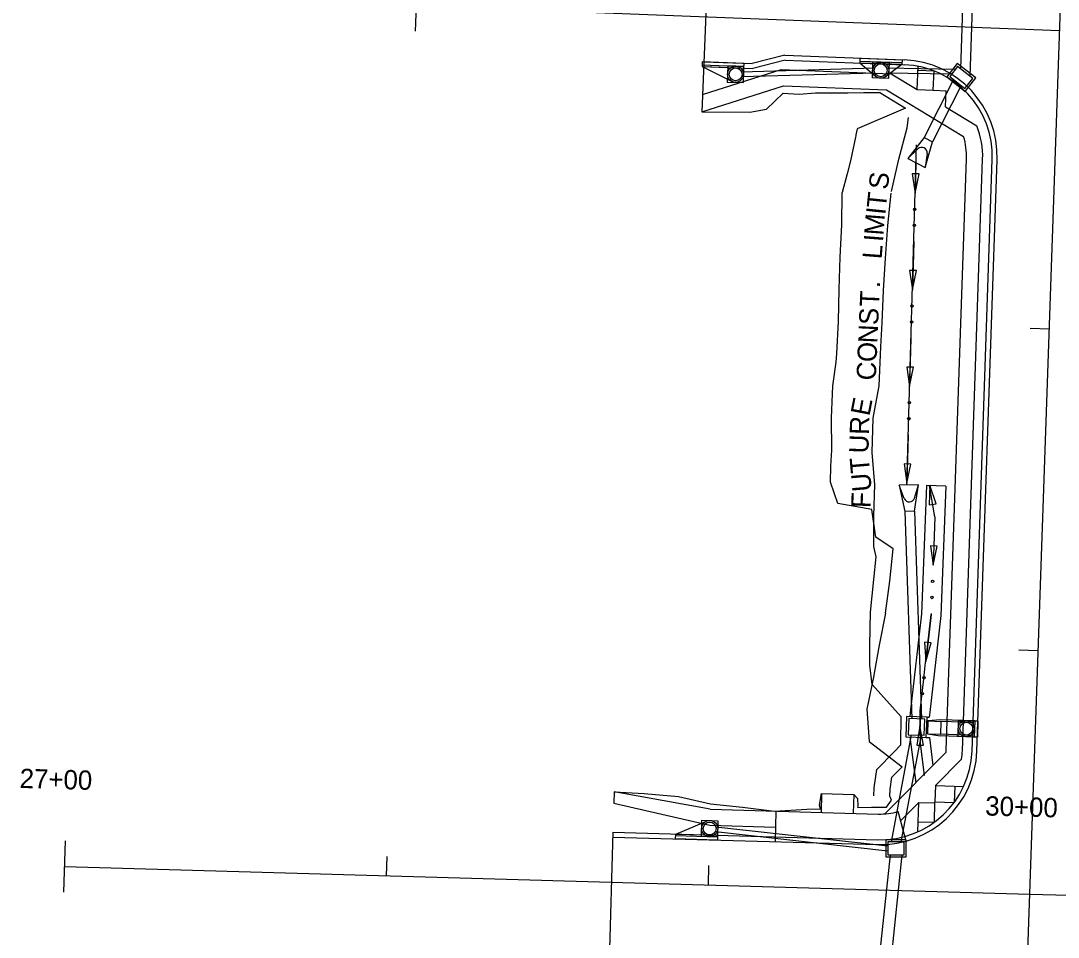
# Model space of a CAD drawing. Extents: x 979959 to 994833, y 1835619 to 1845316.
# Drawn here: x 992166.1 to 992488.3, y 1842864.9 to 1843149.5 of the extents above; entities that cross this region are included whole.
import ezdxf

# ---------------------------------------------------------------- set-up
doc = ezdxf.new("R2010")
doc.units = 0
for name, color, linetype in [('Future 5 Lane Construction Limits', 7, 'Continuous'), ('R_Drainage', 7, 'Continuous'), ('R_Horz Alg', 7, 'Continuous'), ('R_Horz Alg Stationing', 7, 'Continuous'), ('R_Proposed Const Limits', 7, 'Continuous'), ('R_Proposed Road', 7, 'Continuous'), ('R_Special Ditch', 7, 'Continuous')]:
    doc.layers.add(name, color=color, linetype=linetype)

msp = doc.modelspace()

# ---------------------------------------------------------------- linework, layer by layer
at = {"layer": 'Future 5 Lane Construction Limits'}
for points in [[(992436.53, 1843096.52), (992438.78, 1843106.54), (992441.33, 1843116.29), (992441.82, 1843119.43)], [(992430.96, 1842986.25), (992431, 1842994.08), (992431.02, 1842995.67), (992431.34, 1843005.42), (992430.48, 1843015.44), (992430.78, 1843026.13), (992432.7, 1843036.1), (992433.09, 1843045.73), (992433.21, 1843048.3), (992433.55, 1843055.72), (992433.98, 1843065.76), (992434.62, 1843075.83), (992435.4, 1843085.91), (992436.43, 1843095.94)], [(992439.42, 1842924.66), (992439.43, 1842925.27), (992439.46, 1842933.33), (992430.48, 1842943.39), (992429.75, 1842949.42), (992429.79, 1842955.63), (992429.99, 1842965.87), (992431.02, 1842976.06), (992431.75, 1842983.02), (992430.96, 1842986.25)], [(992431.02, 1842908.86), (992431.09, 1842911.37), (992431.93, 1842917.04), (992437.28, 1842922.47), (992439.42, 1842924.66)]]:
    msp.add_lwpolyline(points, dxfattribs=at)
at = {"layer": 'R_Drainage'}
for p, q in [((992458.79, 1843162.87), (992457.93, 1843134.59)), ((992461.79, 1843162.77), (992460.86, 1843132.3)), ((992377.69, 1843135.78), (992390.68, 1843135.27)), ((992426.72, 1843136.37), (992431.51, 1843132.24)), ((992439.73, 1843136.39), (992426.74, 1843136.87)), ((992439.72, 1843135.89), (992434.63, 1843132.12)), ((992377.67, 1843135.28), (992386.97, 1843130.63)), ((992389.92, 1843133.67), (992431.27, 1843134.83)), ((992389.96, 1843132.17), (992431.31, 1843133.33)), ((992434.99, 1843133.35), (992455.23, 1843132.98)), ((992435.01, 1843134.85), (992456.38, 1843134.46)), ((992385.49, 1843130.47), (992390.48, 1843130.28)), ((992435.55, 1843131.54), (992430.55, 1843131.73)), ((992455.74, 1843131.23), (992446.61, 1843113.29)), ((992458.13, 1843129.36), (992449.28, 1843111.93)), ((992446.61, 1843113.29), (992441.58, 1843106.7)), ((992446.61, 1843113.29), (992449.28, 1843111.93)), ((992446.93, 1843103.98), (992449.28, 1843111.93)), ((992444.72, 1843109.74), (992441.58, 1843106.7)), ((992441.58, 1843106.7), (992446.93, 1843103.98)), ((992447.53, 1843108.31), (992446.93, 1843103.98)), ((992444.91, 1843005.46), (992438.91, 1843005.26)), ((992438.91, 1843005.26), (992440.68, 1842997.16)), ((992440.47, 1843001.18), (992438.91, 1843005.26)), ((992443.62, 1843001.28), (992444.91, 1843005.46)), ((992443.68, 1842997.26), (992444.91, 1843005.46)), ((992447.37, 1843005.2), (992445.81, 1842965.33)), ((992453.37, 1843004.96), (992447.37, 1843005.2)), ((992453.37, 1843004.96), (992451.79, 1842964.87)), ((992443.68, 1842997.26), (992440.68, 1842997.16)), ((992440.68, 1842997.16), (992442.84, 1842932.78)), ((992443.68, 1842997.26), (992445.84, 1842932.68)), ((992447.53, 1842933.29), (992448.19, 1842933.27)), ((992447.82, 1842932.1), (992447.68, 1842928.1)), ((992451.84, 1842932.47), (992447.82, 1842932.1)), ((992447.82, 1842932.1), (992451.81, 1842931.97)), ((992451.81, 1842931.97), (992451.68, 1842927.97)), ((992461.81, 1842931.63), (992451.81, 1842931.97)), ((992462.33, 1842932.11), (992451.84, 1842932.47)), ((992457.16, 1842927.29), (992457.33, 1842932.28)), ((992461.81, 1842931.63), (992461.67, 1842927.63)), ((992462.33, 1842932.11), (992462.16, 1842927.11)), ((992442.65, 1842927.79), (992436.36, 1842894.55)), ((992445.68, 1842927.68), (992439.41, 1842894.55)), ((992447.31, 1842926.96), (992448.27, 1842926.93)), ((992447.68, 1842928.1), (992451.66, 1842927.47)), ((992447.68, 1842928.1), (992451.68, 1842927.97)), ((992462.16, 1842927.11), (992451.66, 1842927.47)), ((992461.67, 1842927.63), (992451.68, 1842927.97)), ((992461.66, 1842927.13), (992463.16, 1842927.08)), ((992444.01, 1842912.95), (992449.37, 1842918.32)), ((992369.48, 1842897), (992379.07, 1842901.01)), ((992377.61, 1842901.27), (992382.61, 1842901.13)), ((992381.8, 1842897.75), (992435.39, 1842891.79)), ((992381.96, 1842899.24), (992435.39, 1842893.3)), ((992369.47, 1842896.5), (992382.46, 1842896.13)), ((992436.04, 1842890.55), (992432.38, 1842855.46)), ((992439.73, 1842890.55), (992436.03, 1842855.08))]:
    msp.add_line(p, q, dxfattribs=at)
for points in [[(992377.67, 1843135.28), (992390.66, 1843134.77), (992390.72, 1843136.27), (992377.73, 1843136.77)], [(992439.72, 1843135.89), (992426.72, 1843136.37), (992426.78, 1843137.87), (992439.77, 1843137.39)], [(992435.55, 1843131.54), (992430.55, 1843131.73), (992430.74, 1843136.72), (992435.74, 1843136.54)], [(992453.64, 1843132.03), (992459.42, 1843127.51), (992462.7, 1843131.72), (992456.92, 1843136.23)], [(992385.49, 1843130.47), (992390.48, 1843130.28), (992390.68, 1843135.27), (992385.68, 1843135.47)], [(992454.57, 1843132.14), (992459.3, 1843128.45), (992461.76, 1843131.6), (992457.03, 1843135.29)], [(992447.53, 1842933.29), (992441.2, 1842933.51), (992440.98, 1842927.18), (992447.31, 1842926.96)], [(992446.84, 1842932.65), (992441.84, 1842932.82), (992441.67, 1842927.82), (992446.66, 1842927.65)], [(992457.16, 1842927.29), (992457.33, 1842932.28), (992462.33, 1842932.11), (992462.16, 1842927.11)], [(992461.66, 1842927.13), (992461.83, 1842932.13), (992463.33, 1842932.08), (992463.16, 1842927.08)], [(992377.61, 1842901.27), (992382.61, 1842901.13), (992382.46, 1842896.13), (992377.47, 1842896.27)], [(992369.48, 1842897), (992382.48, 1842896.63), (992382.44, 1842895.13), (992369.44, 1842895.5)], [(992441.05, 1842889.88), (992441.05, 1842895.22), (992434.72, 1842895.22), (992434.72, 1842889.88)], [(992440.39, 1842890.55), (992440.39, 1842894.55), (992435.39, 1842894.55), (992435.39, 1842890.55)]]:
    msp.add_lwpolyline(points, close=True, dxfattribs=at)
for points in [[(992445.81, 1842965.33), (992444.68, 1842955.47), (992442.41, 1842935.54), (992442.17, 1842933.47)], [(992451.79, 1842964.87), (992450.64, 1842954.79), (992448.37, 1842934.86), (992448.19, 1842933.27)], [(992463.16, 1842927.08), (992463.33, 1842932.08), (992461.83, 1842932.13), (992461.66, 1842927.13)], [(992442.19, 1842927.14), (992444.01, 1842912.93)], [(992448.27, 1842926.93), (992449.37, 1842918.32)]]:
    msp.add_lwpolyline(points, dxfattribs=at)
for centre, radius in [((992433.15, 1843134.13), 2.5), ((992433.15, 1843134.13), 2.5), ((992433.15, 1843134.13), 2), ((992433.15, 1843134.13), 2), ((992388.08, 1843132.87), 2.5), ((992388.08, 1843132.87), 2.5), ((992388.08, 1843132.87), 2), ((992388.08, 1843132.87), 2), ((992459.74, 1842929.7), 2.5), ((992459.74, 1842929.7), 2.5), ((992459.74, 1842929.7), 2), ((992459.74, 1842929.7), 2), ((992380.04, 1842898.7), 2.5), ((992380.04, 1842898.7), 2.5), ((992380.04, 1842898.7), 2), ((992380.04, 1842898.7), 2)]:
    msp.add_circle(centre, radius, dxfattribs=at)
for centre, start, end in [((992445.88, 1843108.54), 352.0964, 134.0112), ((992442.03, 1843001.77), 200.9572, 342.8719)]:
    msp.add_arc(centre, 1.67, start, end, dxfattribs=at)
at = {"layer": 'R_Horz Alg'}
for p, q in [((992476.02, 1842777.04), (992513.51, 1843870.41)), ((992288.84, 1843154.22), (992488.69, 1843146.49)), ((992179.62, 1842886.9), (992479.5, 1842878.36)), ((992479.5, 1842878.36), (992779.37, 1842869.83))]:
    msp.add_line(p, q, dxfattribs=at)
at = {"layer": 'R_Horz Alg Stationing'}
for points in [[(992289.15, 1843162.21), (992288.53, 1843146.23)], [(992479.52, 1843054.1), (992485.51, 1843053.89)], [(992476.09, 1842954.16), (992482.09, 1842953.95)], [(992179.84, 1842894.9), (992179.39, 1842878.9)], [(992279.75, 1842890.05), (992279.58, 1842884.05)], [(992379.71, 1842887.21), (992379.54, 1842881.21)]]:
    msp.add_lwpolyline(points, dxfattribs=at)
at = {"layer": 'R_Proposed Const Limits'}
for points in [[(992377.63, 1843121.23), (992392.51, 1843121.11), (992397.68, 1843122.08), (992402.87, 1843126.97), (992407.87, 1843126.72), (992412.89, 1843127.14), (992417.89, 1843127.14), (992422.89, 1843127.16), (992427.9, 1843127.19), (992432.9, 1843127.23), (992440.86, 1843122.31)], [(992440.86, 1843122.31), (992425.86, 1843115.97), (992425.46, 1843114.11), (992425.38, 1843113.73), (992425.31, 1843113.4), (992423.73, 1843106.04), (992422.7, 1843102.01), (992421.2, 1843096.12)], [(992419.85, 1842999.62), (992417.52, 1843006.19), (992417.66, 1843011.19), (992417.92, 1843016.19), (992417.87, 1843026.19), (992418.25, 1843036.19), (992419.31, 1843043.53), (992419.56, 1843046.15), (992420.02, 1843056.14), (992420.25, 1843066.14), (992420.51, 1843076.13), (992421.12, 1843086.12), (992421.2, 1843096.12)], [(992434.63, 1842965.58), (992435.99, 1842975.54), (992437.04, 1842985.51), (992431.58, 1842989.13), (992430.37, 1842997.79), (992419.85, 1842999.62)], [(992434.63, 1842965.58), (992432.66, 1842955.65), (992431.58, 1842949.82), (992430.86, 1842945.7), (992428.85, 1842935.76), (992429.61, 1842925.73), (992439.8, 1842917.89)], [(992436.01, 1842908.71), (992436.08, 1842910.93), (992436.63, 1842914.69), (992439.8, 1842917.89)], [(992350.35, 1842910.08), (992359.72, 1842909.58), (992370.31, 1842908.66), (992380.25, 1842906.33), (992390.23, 1842905.36), (992400.2, 1842904.14)], [(992414.48, 1842904.81), (992414.12, 1842905.92), (992414.79, 1842909.56)], [(992425.99, 1842907.9), (992424.78, 1842909.28)], [(992426.04, 1842905.19), (992426.1, 1842905.89), (992425.99, 1842907.9)], [(992426.04, 1842905.19), (992430.24, 1842905.31), (992434.94, 1842905.31), (992436.45, 1842907.46), (992436.01, 1842908.71)], [(992400.2, 1842904.14), (992410.22, 1842904.67), (992414.48, 1842904.81)]]:
    msp.add_lwpolyline(points, dxfattribs=at)
at = {"layer": 'R_Proposed Road'}
for p, q in [((992379.76, 1843176.2), (992377.63, 1843121.23)), ((992378.23, 1843136.75), (992393.22, 1843136.17)), ((992403.33, 1843138.79), (992393.22, 1843136.17)), ((992403.49, 1843137.28), (992393.38, 1843134.67)), ((992403.33, 1843138.79), (992440.48, 1843137.35)), ((992403.49, 1843137.28), (992440.42, 1843135.85)), ((992377.84, 1843126.55), (992402.28, 1843134.32)), ((992378.17, 1843135.25), (992393.38, 1843134.67)), ((992402.28, 1843134.32), (992436.42, 1843133)), ((992436.42, 1843133), (992444.48, 1843128.11)), ((992444.48, 1843128.11), (992444.76, 1843135.35)), ((992444.71, 1843134.11), (992449.71, 1843133.91)), ((992449.47, 1843127.92), (992449.71, 1843133.91)), ((992377.63, 1843121.23), (992402.96, 1843129.29)), ((992402.96, 1843129.29), (992434.93, 1843128.06)), ((992434.93, 1843128.06), (992458.88, 1843113.52)), ((992444.48, 1843128.11), (992449.47, 1843127.92)), ((992449.47, 1843127.92), (992453.47, 1843127.76)), ((992453.28, 1843122.77), (992453.47, 1843127.76)), ((992453.28, 1843122.77), (992462.98, 1843116.87)), ((992453.51, 1842923), (992459.81, 1843106.67)), ((992458.51, 1842922.83), (992464.8, 1843106.5)), ((992461.51, 1842922.73), (992467.8, 1843106.4)), ((992463, 1842922.68), (992469.3, 1843106.34)), ((992453.48, 1842922.46), (992434.39, 1842903.25)), ((992458.28, 1842920.2), (992450.16, 1842912.02)), ((992450.16, 1842912.02), (992449.98, 1842907.02)), ((992450.16, 1842912.02), (992458.88, 1842911.72)), ((992456.15, 1842911.81), (992455.98, 1842906.82)), ((992350.35, 1842910.08), (992350.25, 1842906.62)), ((992380.2, 1842904.7), (992350.35, 1842910.08)), ((992414.79, 1842909.56), (992414.62, 1842903.72)), ((992414.79, 1842909.56), (992424.78, 1842909.28)), ((992424.78, 1842909.28), (992424.61, 1842903.43)), ((992449.8, 1842900.67), (992449.98, 1842907.02)), ((992449.98, 1842907.02), (992455.98, 1842906.82)), ((992350.25, 1842906.62), (992380.06, 1842899.7)), ((992380.2, 1842904.7), (992432.44, 1842903.21)), ((992400.62, 1842904.12), (992400.35, 1842894.62)), ((992441.1, 1842894.81), (992438.54, 1842903.96)), ((992444.98, 1842906.81), (992439.33, 1842901.13)), ((992444.72, 1842897.71), (992444.98, 1842906.81)), ((992444.98, 1842906.81), (992449.97, 1842906.67)), ((992444.81, 1842900.81), (992449.8, 1842900.67)), ((992349.99, 1842897.56), (992348.65, 1842850.57)), ((992349.99, 1842897.56), (992432.21, 1842895.22)), ((992380.06, 1842899.7), (992400.48, 1842899.12)), ((992349.95, 1842896.06), (992432.17, 1842893.72))]:
    msp.add_line(p, q, dxfattribs=at)
for centre, radius, start, end in [((992439.32, 1843107.37), 28.5, 358.0361, 87.7861), ((992439.32, 1843107.37), 30, 358.0361, 87.7861), ((992439.32, 1843107.37), 25.5, 358.0361, 21.8732), ((992439.32, 1843107.37), 20.5, 358.0361, 17.4406), ((992433.02, 1842923.7), 20.5, 356.5314, 358.0361), ((992433.02, 1842923.7), 30, 268.3694, 358.0361), ((992433.02, 1842923.7), 28.5, 268.3694, 358.0361), ((992433.02, 1842923.7), 25.5, 352.092, 358.0361), ((992433.02, 1842923.7), 20.5, 268.3694, 285.6222)]:
    msp.add_arc(centre, radius, start, end, dxfattribs=at)
at = {"layer": 'R_Special Ditch'}
for p, q in [((992445.06, 1843101.95), (992442.94, 1843102.01)), ((992442.94, 1843102.01), (992443.83, 1843095.98)), ((992443.83, 1843095.98), (992445.06, 1843101.95)), ((992444.21, 1843071.92), (992442.09, 1843071.98)), ((992442.09, 1843071.98), (992442.98, 1843065.95)), ((992442.98, 1843065.95), (992444.21, 1843071.92)), ((992443.36, 1843041.89), (992441.24, 1843041.95)), ((992441.24, 1843041.95), (992442.13, 1843035.93)), ((992442.13, 1843035.93), (992443.36, 1843041.89)), ((992442.51, 1843011.87), (992440.39, 1843011.93)), ((992440.39, 1843011.93), (992441.28, 1843005.9)), ((992441.28, 1843005.9), (992442.51, 1843011.87)), ((992448.36, 1843005.31), (992448.24, 1842999.22)), ((992449.99, 1842995.44), (992448.31, 1843005.14)), ((992450.33, 1842999.54), (992448.36, 1843005.31)), ((992448.24, 1842999.22), (992450.33, 1842999.54)), ((992450.7, 1842986.4), (992448.58, 1842986.49)), ((992448.58, 1842986.49), (992449.4, 1842980.45)), ((992449.4, 1842980.45), (992450.7, 1842986.4)), ((992448.86, 1842956.36), (992446.76, 1842956.6)), ((992446.76, 1842956.6), (992447.13, 1842950.52)), ((992447.13, 1842950.52), (992448.86, 1842956.36)), ((992445.3, 1842930.57), (992444.37, 1842924.55)), ((992446.48, 1842924.6), (992445.3, 1842930.57)), ((992444.37, 1842924.55), (992446.48, 1842924.6))]:
    msp.add_line(p, q, dxfattribs=at)
for points in [[(992441.26, 1843005.36), (992444.26, 1843110.97)], [(992444.1, 1843105.42), (992443.83, 1843095.98)], [(992443.4, 1843080.95), (992442.98, 1843065.95)], [(992443.41, 1843080.98), (992443.4, 1843080.95)], [(992442.55, 1843050.92), (992442.13, 1843035.93)], [(992442.55, 1843050.96), (992442.55, 1843050.92)], [(992441.7, 1843020.89), (992441.28, 1843005.9)], [(992441.7, 1843020.93), (992441.7, 1843020.9)], [(992449.99, 1842995.44), (992448.31, 1843005.14)], [(992449.99, 1842995.44), (992449.4, 1842980.45)], [(992445.43, 1842930.19), (992445.39, 1842935.2), (992446.52, 1842945.16), (992446.99, 1842949.29), (992447.66, 1842955.13), (992448.8, 1842965.1)], [(992448.81, 1842965.42), (992448.8, 1842965.1), (992447.66, 1842955.13), (992447.13, 1842950.52)], [(992448.82, 1842965.46), (992448.81, 1842965.42)], [(992445.43, 1842935.58), (992445.39, 1842935.2), (992445.43, 1842930.19)], [(992445.43, 1842935.61), (992445.43, 1842935.58)], [(992445.43, 1842930.24), (992445.43, 1842930.19)], [(992446.76, 1842915.14), (992445.46, 1842925.19), (992445.43, 1842930.19)], [(992446.12, 1842920.05), (992445.46, 1842925.19), (992445.43, 1842930.19)]]:
    msp.add_lwpolyline(points, dxfattribs=at)
for centre in [(992443.72, 1843090.97), (992443.58, 1843085.97), (992442.87, 1843060.95), (992442.73, 1843055.94), (992442.02, 1843030.92), (992441.88, 1843025.91), (992449.24, 1842975.45), (992449.05, 1842970.44), (992446.6, 1842945.54), (992446.03, 1842940.56)]:
    msp.add_circle(centre, 0.375, dxfattribs=at)

# ---------------------------------------------------------------- texts
at = {"layer": 'Future 5 Lane Construction Limits'}
for s, rotation, p in [('S', 84.0928, (992435.35, 1843096.9)), ('T', 84.0928, (992434.75, 1843091.08)), ('I', 84.0928, (992434.55, 1843089.1)), ('M', 85.6236, (992433.98, 1843082.7)), ('I', 85.6236, (992433.83, 1843080.72)), ('L', 85.6236, (992433.42, 1843075.35)), ('.', 86.3303, (992432.86, 1843066.44)), ('T', 87.5452, (992432.6, 1843060.59)), ('S', 87.5452, (992432.36, 1843054.93)), ('N', 87.4106, (992432.1, 1843049.26)), ('O', 87.369, (992431.83, 1843043.41)), ('C', 87.6545, (992431.61, 1843037.74)), ('E', 79.1278, (992429.63, 1843026.54)), ('R', 88.3765, (992429.49, 1843020.88)), ('U', 88.3765, (992429.32, 1843015.11)), ('T', 94.9012, (992429.87, 1843009.28)), ('U', 94.9012, (992430.37, 1843003.54)), ('F', 88.1095, (992429.95, 1842998.15))]:
    msp.add_text(s, height=6, rotation=rotation, dxfattribs=at).set_placement(p)
at = {"layer": 'R_Horz Alg Stationing'}
for s, p in [('27+00', (992165.66, 1842911.31)), ('30+00', (992465.54, 1842902.77))]:
    msp.add_text(s, height=6, rotation=358.3694, dxfattribs=at).set_placement(p)

doc.saveas('drawing.dxf')
